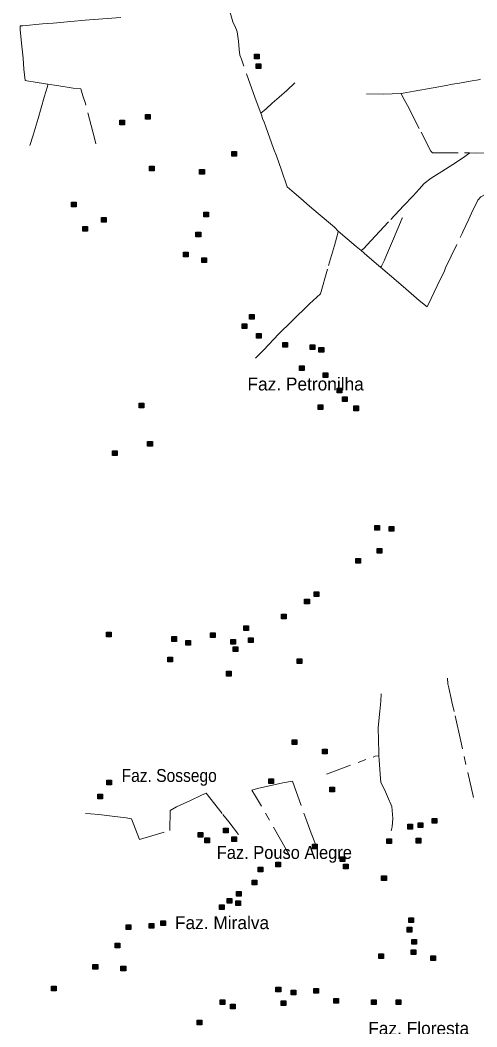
# Model space of a CAD drawing. Extents: x 393.5 to 446.9, y 8064.8 to 8120.4.
# Drawn here: x 401.4 to 407.05, y 8086.21 to 8098.67 of the extents above; entities that cross this region are included whole.
import ezdxf

# ---------------------------------------------------------------- set-up
doc = ezdxf.new("R2010")
doc.units = 0
doc.header["$LTSCALE"] = 0.064
doc.linetypes.add('DOT_DASHED', pattern=[7.7, 5, -1.2, 0.3, -1.2])
doc.layers.add('2', color=7, linetype='Continuous', lineweight=25)
doc.layers.add('22', color=7, linetype='DOT_DASHED', lineweight=13)
doc.layers.add('61', color=7, linetype='Continuous')

msp = doc.modelspace()

# ---------------------------------------------------------------- hatches: boundary and pattern name
at = {"layer": '2'}
for points in [[(404.302, 8098.2488), (404.36, 8098.2488), (404.36, 8098.1908), (404.302, 8098.1908)], [(404.3231, 8098.1292), (404.3811, 8098.1292), (404.3811, 8098.0712), (404.3231, 8098.0712)], [(402.9537, 8097.5023), (403.0117, 8097.5023), (403.0117, 8097.4443), (402.9537, 8097.4443)], [(402.6377, 8097.4316), (402.6957, 8097.4316), (402.6957, 8097.3736), (402.6377, 8097.3736)], [(404.0237, 8097.0426), (404.0817, 8097.0426), (404.0817, 8096.9846), (404.0237, 8096.9846)], [(403.0032, 8096.8617), (403.0612, 8096.8617), (403.0612, 8096.8037), (403.0032, 8096.8037)], [(403.6247, 8096.822), (403.6827, 8096.822), (403.6827, 8096.764), (403.6247, 8096.764)], [(402.0408, 8096.4174), (402.0988, 8096.4174), (402.0988, 8096.3594), (402.0408, 8096.3594)], [(402.4106, 8096.2273), (402.4686, 8096.2273), (402.4686, 8096.1693), (402.4106, 8096.1693)], [(403.6778, 8096.2912), (403.7358, 8096.2912), (403.7358, 8096.2332), (403.6778, 8096.2332)], [(402.1813, 8096.1145), (402.2393, 8096.1145), (402.2393, 8096.0565), (402.1813, 8096.0565)], [(403.5795, 8096.0448), (403.6375, 8096.0448), (403.6375, 8095.9868), (403.5795, 8095.9868)], [(403.4244, 8095.7975), (403.4824, 8095.7975), (403.4824, 8095.7395), (403.4244, 8095.7395)], [(403.65, 8095.7277), (403.708, 8095.7277), (403.708, 8095.6697), (403.65, 8095.6697)], [(404.2404, 8095.0263), (404.2984, 8095.0263), (404.2984, 8094.9683), (404.2404, 8094.9683)], [(404.1492, 8094.9105), (404.2072, 8094.9105), (404.2072, 8094.8525), (404.1492, 8094.8525)], [(404.3285, 8094.7903), (404.3865, 8094.7903), (404.3865, 8094.7323), (404.3285, 8094.7323)], [(404.6548, 8094.6775), (404.7128, 8094.6775), (404.7128, 8094.6195), (404.6548, 8094.6195)], [(404.9925, 8094.65), (405.0505, 8094.65), (405.0505, 8094.592), (404.9925, 8094.592)], [(405.1008, 8094.6177), (405.1588, 8094.6177), (405.1588, 8094.5597), (405.1008, 8094.5597)], [(404.859, 8094.3885), (404.917, 8094.3885), (404.917, 8094.3305), (404.859, 8094.3305)], [(405.1537, 8094.3047), (405.2117, 8094.3047), (405.2117, 8094.2467), (405.1537, 8094.2467)], [(405.324, 8094.1142), (405.382, 8094.1142), (405.382, 8094.0562), (405.324, 8094.0562)], [(405.3916, 8094.005), (405.4496, 8094.005), (405.4496, 8093.947), (405.3916, 8093.947)], [(402.8759, 8093.9275), (402.9339, 8093.9275), (402.9339, 8093.8695), (402.8759, 8093.8695)], [(405.0893, 8093.9068), (405.1473, 8093.9068), (405.1473, 8093.8488), (405.0893, 8093.8488)], [(405.5314, 8093.8928), (405.5894, 8093.8928), (405.5894, 8093.8348), (405.5314, 8093.8348)], [(402.5459, 8093.3388), (402.6039, 8093.3388), (402.6039, 8093.2808), (402.5459, 8093.2808)], [(402.9816, 8093.4521), (403.0396, 8093.4521), (403.0396, 8093.3941), (402.9816, 8093.3941)], [(405.792, 8092.414), (405.85, 8092.414), (405.85, 8092.356), (405.792, 8092.356)], [(405.9672, 8092.4), (406.0252, 8092.4), (406.0252, 8092.342), (405.9672, 8092.342)], [(405.8208, 8092.1275), (405.8788, 8092.1275), (405.8788, 8092.0695), (405.8208, 8092.0695)], [(405.5557, 8092.0035), (405.6137, 8092.0035), (405.6137, 8091.9455), (405.5557, 8091.9455)], [(405.0426, 8091.5927), (405.1006, 8091.5927), (405.1006, 8091.5347), (405.0426, 8091.5347)], [(404.9233, 8091.5012), (404.9813, 8091.5012), (404.9813, 8091.4432), (404.9233, 8091.4432)], [(404.6388, 8091.3169), (404.6968, 8091.3169), (404.6968, 8091.2589), (404.6388, 8091.2589)], [(402.4716, 8091.0928), (402.5296, 8091.0928), (402.5296, 8091.0348), (402.4716, 8091.0348)], [(404.1693, 8091.1691), (404.2273, 8091.1691), (404.2273, 8091.1111), (404.1693, 8091.1111)], [(403.2804, 8091.0368), (403.3384, 8091.0368), (403.3384, 8090.9788), (403.2804, 8090.9788)], [(403.4555, 8090.9884), (403.5135, 8090.9884), (403.5135, 8090.9304), (403.4555, 8090.9304)], [(403.7582, 8091.086), (403.8162, 8091.086), (403.8162, 8091.028), (403.7582, 8091.028)], [(404.0109, 8091.0018), (404.0689, 8091.0018), (404.0689, 8090.9438), (404.0109, 8090.9438)], [(404.2287, 8091.023), (404.2867, 8091.023), (404.2867, 8090.965), (404.2287, 8090.965)], [(404.0391, 8090.9105), (404.0971, 8090.9105), (404.0971, 8090.8525), (404.0391, 8090.8525)], [(403.2318, 8090.781), (403.2898, 8090.781), (403.2898, 8090.723), (403.2318, 8090.723)], [(404.8322, 8090.7629), (404.8902, 8090.7629), (404.8902, 8090.7049), (404.8322, 8090.7049)], [(403.9548, 8090.6076), (404.0128, 8090.6076), (404.0128, 8090.5496), (403.9548, 8090.5496)], [(404.7686, 8089.7584), (404.8266, 8089.7584), (404.8266, 8089.7004), (404.7686, 8089.7004)], [(405.1425, 8089.6457), (405.2005, 8089.6457), (405.2005, 8089.5877), (405.1425, 8089.5877)], [(402.4769, 8089.2584), (402.5349, 8089.2584), (402.5349, 8089.2004), (402.4769, 8089.2004)], [(404.4821, 8089.2773), (404.5401, 8089.2773), (404.5401, 8089.2193), (404.4821, 8089.2193)], [(405.2354, 8089.1725), (405.2934, 8089.1725), (405.2934, 8089.1145), (405.2354, 8089.1145)], [(402.3662, 8089.0853), (402.4242, 8089.0853), (402.4242, 8089.0273), (402.3662, 8089.0273)], [(406.3291, 8088.7332), (406.3871, 8088.7332), (406.3871, 8088.6752), (406.3291, 8088.6752)], [(406.4992, 8088.7842), (406.5572, 8088.7842), (406.5572, 8088.7262), (406.4992, 8088.7262)], [(403.608, 8088.6124), (403.666, 8088.6124), (403.666, 8088.5544), (403.608, 8088.5544)], [(403.9209, 8088.6675), (403.9789, 8088.6675), (403.9789, 8088.6095), (403.9209, 8088.6095)], [(406.1977, 8088.7131), (406.2557, 8088.7131), (406.2557, 8088.6551), (406.1977, 8088.6551)], [(403.6897, 8088.544), (403.7477, 8088.544), (403.7477, 8088.486), (403.6897, 8088.486)], [(404.0222, 8088.5586), (404.0802, 8088.5586), (404.0802, 8088.5006), (404.0222, 8088.5006)], [(405.9402, 8088.5332), (405.9982, 8088.5332), (405.9982, 8088.4752), (405.9402, 8088.4752)], [(406.3036, 8088.5398), (406.3616, 8088.5398), (406.3616, 8088.4818), (406.3036, 8088.4818)], [(405.0197, 8088.4675), (405.0777, 8088.4675), (405.0777, 8088.4095), (405.0197, 8088.4095)], [(404.5674, 8088.2454), (404.6254, 8088.2454), (404.6254, 8088.1874), (404.5674, 8088.1874)], [(405.3621, 8088.3107), (405.4201, 8088.3107), (405.4201, 8088.2527), (405.3621, 8088.2527)], [(404.3475, 8088.1816), (404.4055, 8088.1816), (404.4055, 8088.1236), (404.3475, 8088.1236)], [(405.4034, 8088.2187), (405.4614, 8088.2187), (405.4614, 8088.1607), (405.4034, 8088.1607)], [(404.2722, 8088.0235), (404.3302, 8088.0235), (404.3302, 8087.9655), (404.2722, 8087.9655)], [(405.8757, 8088.0757), (405.9337, 8088.0757), (405.9337, 8088.0177), (405.8757, 8088.0177)], [(404.0812, 8087.8829), (404.1392, 8087.8829), (404.1392, 8087.8249), (404.0812, 8087.8249)], [(403.9646, 8087.7946), (404.0226, 8087.7946), (404.0226, 8087.7366), (403.9646, 8087.7366)], [(404.0734, 8087.7653), (404.1314, 8087.7653), (404.1314, 8087.7073), (404.0734, 8087.7073)], [(403.8705, 8087.7147), (403.9285, 8087.7147), (403.9285, 8087.6567), (403.8705, 8087.6567)], [(403, 8087.4867), (403.058, 8087.4867), (403.058, 8087.4287), (403, 8087.4287)], [(403.1449, 8087.5175), (403.2029, 8087.5175), (403.2029, 8087.4595), (403.1449, 8087.4595)], [(406.2113, 8087.5568), (406.2693, 8087.5568), (406.2693, 8087.4988), (406.2113, 8087.4988)], [(402.7152, 8087.4706), (402.7732, 8087.4706), (402.7732, 8087.4126), (402.7152, 8087.4126)], [(406.1901, 8087.4378), (406.2481, 8087.4378), (406.2481, 8087.3798), (406.1901, 8087.3798)], [(402.5805, 8087.2434), (402.6385, 8087.2434), (402.6385, 8087.1854), (402.5805, 8087.1854)], [(406.247, 8087.2871), (406.305, 8087.2871), (406.305, 8087.2291), (406.247, 8087.2291)], [(405.8389, 8087.1089), (405.8969, 8087.1089), (405.8969, 8087.0509), (405.8389, 8087.0509)], [(406.2407, 8087.1575), (406.2987, 8087.1575), (406.2987, 8087.0995), (406.2407, 8087.0995)], [(406.4839, 8087.084), (406.5419, 8087.084), (406.5419, 8087.026), (406.4839, 8087.026)], [(402.3055, 8086.9766), (402.3635, 8086.9766), (402.3635, 8086.9186), (402.3055, 8086.9186)], [(402.6517, 8086.9574), (402.7097, 8086.9574), (402.7097, 8086.8994), (402.6517, 8086.8994)], [(401.7937, 8086.708), (401.8517, 8086.708), (401.8517, 8086.65), (401.7937, 8086.65)], [(404.5689, 8086.6965), (404.6269, 8086.6965), (404.6269, 8086.6385), (404.5689, 8086.6385)], [(404.7581, 8086.6615), (404.8161, 8086.6615), (404.8161, 8086.6035), (404.7581, 8086.6035)], [(405.0387, 8086.6824), (405.0967, 8086.6824), (405.0967, 8086.6244), (405.0387, 8086.6244)], [(403.8774, 8086.5412), (403.9354, 8086.5412), (403.9354, 8086.4832), (403.8774, 8086.4832)], [(404.0075, 8086.4862), (404.0655, 8086.4862), (404.0655, 8086.4282), (404.0075, 8086.4282)], [(404.6317, 8086.5284), (404.6897, 8086.5284), (404.6897, 8086.4704), (404.6317, 8086.4704)], [(405.2839, 8086.5561), (405.3419, 8086.5561), (405.3419, 8086.4981), (405.2839, 8086.4981)], [(405.7515, 8086.5395), (405.8095, 8086.5395), (405.8095, 8086.4815), (405.7515, 8086.4815)], [(406.0551, 8086.5412), (406.1131, 8086.5412), (406.1131, 8086.4832), (406.0551, 8086.4832)], [(403.5933, 8086.2898), (403.6513, 8086.2898), (403.6513, 8086.2318), (403.5933, 8086.2318)]]:
    msp.add_hatch(color=256, dxfattribs=at).paths.add_polyline_path(points)

# ---------------------------------------------------------------- linework, layer by layer
for points in [[(404.302, 8098.2488), (404.36, 8098.2488), (404.36, 8098.1908), (404.302, 8098.1908)], [(404.3231, 8098.1292), (404.3811, 8098.1292), (404.3811, 8098.0712), (404.3231, 8098.0712)], [(402.9537, 8097.5023), (403.0117, 8097.5023), (403.0117, 8097.4443), (402.9537, 8097.4443)], [(402.6377, 8097.4316), (402.6957, 8097.4316), (402.6957, 8097.3736), (402.6377, 8097.3736)], [(404.0237, 8097.0426), (404.0817, 8097.0426), (404.0817, 8096.9846), (404.0237, 8096.9846)], [(403.0032, 8096.8617), (403.0612, 8096.8617), (403.0612, 8096.8037), (403.0032, 8096.8037)], [(403.6247, 8096.822), (403.6827, 8096.822), (403.6827, 8096.764), (403.6247, 8096.764)], [(402.0408, 8096.4174), (402.0988, 8096.4174), (402.0988, 8096.3594), (402.0408, 8096.3594)], [(402.4106, 8096.2273), (402.4686, 8096.2273), (402.4686, 8096.1693), (402.4106, 8096.1693)], [(403.6778, 8096.2912), (403.7358, 8096.2912), (403.7358, 8096.2332), (403.6778, 8096.2332)], [(402.1813, 8096.1145), (402.2393, 8096.1145), (402.2393, 8096.0565), (402.1813, 8096.0565)], [(403.5795, 8096.0448), (403.6375, 8096.0448), (403.6375, 8095.9868), (403.5795, 8095.9868)], [(403.4244, 8095.7975), (403.4824, 8095.7975), (403.4824, 8095.7395), (403.4244, 8095.7395)], [(403.65, 8095.7277), (403.708, 8095.7277), (403.708, 8095.6697), (403.65, 8095.6697)], [(404.2404, 8095.0263), (404.2984, 8095.0263), (404.2984, 8094.9683), (404.2404, 8094.9683)], [(404.1492, 8094.9105), (404.2072, 8094.9105), (404.2072, 8094.8525), (404.1492, 8094.8525)], [(404.3285, 8094.7903), (404.3865, 8094.7903), (404.3865, 8094.7323), (404.3285, 8094.7323)], [(404.6548, 8094.6775), (404.7128, 8094.6775), (404.7128, 8094.6195), (404.6548, 8094.6195)], [(404.9925, 8094.65), (405.0505, 8094.65), (405.0505, 8094.592), (404.9925, 8094.592)], [(405.1008, 8094.6177), (405.1588, 8094.6177), (405.1588, 8094.5597), (405.1008, 8094.5597)], [(404.859, 8094.3885), (404.917, 8094.3885), (404.917, 8094.3305), (404.859, 8094.3305)], [(405.1537, 8094.3047), (405.2117, 8094.3047), (405.2117, 8094.2467), (405.1537, 8094.2467)], [(405.324, 8094.1142), (405.382, 8094.1142), (405.382, 8094.0562), (405.324, 8094.0562)], [(405.3916, 8094.005), (405.4496, 8094.005), (405.4496, 8093.947), (405.3916, 8093.947)], [(402.8759, 8093.9275), (402.9339, 8093.9275), (402.9339, 8093.8695), (402.8759, 8093.8695)], [(405.0893, 8093.9068), (405.1473, 8093.9068), (405.1473, 8093.8488), (405.0893, 8093.8488)], [(405.5314, 8093.8928), (405.5894, 8093.8928), (405.5894, 8093.8348), (405.5314, 8093.8348)], [(402.5459, 8093.3388), (402.6039, 8093.3388), (402.6039, 8093.2808), (402.5459, 8093.2808)], [(402.9816, 8093.4521), (403.0396, 8093.4521), (403.0396, 8093.3941), (402.9816, 8093.3941)], [(405.792, 8092.414), (405.85, 8092.414), (405.85, 8092.356), (405.792, 8092.356)], [(405.9672, 8092.4), (406.0252, 8092.4), (406.0252, 8092.342), (405.9672, 8092.342)], [(405.8208, 8092.1275), (405.8788, 8092.1275), (405.8788, 8092.0695), (405.8208, 8092.0695)], [(405.5557, 8092.0035), (405.6137, 8092.0035), (405.6137, 8091.9455), (405.5557, 8091.9455)], [(405.0426, 8091.5927), (405.1006, 8091.5927), (405.1006, 8091.5347), (405.0426, 8091.5347)], [(404.9233, 8091.5012), (404.9813, 8091.5012), (404.9813, 8091.4432), (404.9233, 8091.4432)], [(404.6388, 8091.3169), (404.6968, 8091.3169), (404.6968, 8091.2589), (404.6388, 8091.2589)], [(402.4716, 8091.0928), (402.5296, 8091.0928), (402.5296, 8091.0348), (402.4716, 8091.0348)], [(404.1693, 8091.1691), (404.2273, 8091.1691), (404.2273, 8091.1111), (404.1693, 8091.1111)], [(403.2804, 8091.0368), (403.3384, 8091.0368), (403.3384, 8090.9788), (403.2804, 8090.9788)], [(403.4555, 8090.9884), (403.5135, 8090.9884), (403.5135, 8090.9304), (403.4555, 8090.9304)], [(403.7582, 8091.086), (403.8162, 8091.086), (403.8162, 8091.028), (403.7582, 8091.028)], [(404.0109, 8091.0018), (404.0689, 8091.0018), (404.0689, 8090.9438), (404.0109, 8090.9438)], [(404.2287, 8091.023), (404.2867, 8091.023), (404.2867, 8090.965), (404.2287, 8090.965)], [(404.0391, 8090.9105), (404.0971, 8090.9105), (404.0971, 8090.8525), (404.0391, 8090.8525)], [(403.2318, 8090.781), (403.2898, 8090.781), (403.2898, 8090.723), (403.2318, 8090.723)], [(404.8322, 8090.7629), (404.8902, 8090.7629), (404.8902, 8090.7049), (404.8322, 8090.7049)], [(403.9548, 8090.6076), (404.0128, 8090.6076), (404.0128, 8090.5496), (403.9548, 8090.5496)], [(404.7686, 8089.7584), (404.8266, 8089.7584), (404.8266, 8089.7004), (404.7686, 8089.7004)], [(405.1425, 8089.6457), (405.2005, 8089.6457), (405.2005, 8089.5877), (405.1425, 8089.5877)], [(402.4769, 8089.2584), (402.5349, 8089.2584), (402.5349, 8089.2004), (402.4769, 8089.2004)], [(404.4821, 8089.2773), (404.5401, 8089.2773), (404.5401, 8089.2193), (404.4821, 8089.2193)], [(405.2354, 8089.1725), (405.2934, 8089.1725), (405.2934, 8089.1145), (405.2354, 8089.1145)], [(402.3662, 8089.0853), (402.4242, 8089.0853), (402.4242, 8089.0273), (402.3662, 8089.0273)], [(406.3291, 8088.7332), (406.3871, 8088.7332), (406.3871, 8088.6752), (406.3291, 8088.6752)], [(406.4992, 8088.7842), (406.5572, 8088.7842), (406.5572, 8088.7262), (406.4992, 8088.7262)], [(403.608, 8088.6124), (403.666, 8088.6124), (403.666, 8088.5544), (403.608, 8088.5544)], [(403.9209, 8088.6675), (403.9789, 8088.6675), (403.9789, 8088.6095), (403.9209, 8088.6095)], [(406.1977, 8088.7131), (406.2557, 8088.7131), (406.2557, 8088.6551), (406.1977, 8088.6551)], [(403.6897, 8088.544), (403.7477, 8088.544), (403.7477, 8088.486), (403.6897, 8088.486)], [(404.0222, 8088.5586), (404.0802, 8088.5586), (404.0802, 8088.5006), (404.0222, 8088.5006)], [(405.9402, 8088.5332), (405.9982, 8088.5332), (405.9982, 8088.4752), (405.9402, 8088.4752)], [(406.3036, 8088.5398), (406.3616, 8088.5398), (406.3616, 8088.4818), (406.3036, 8088.4818)], [(405.0197, 8088.4675), (405.0777, 8088.4675), (405.0777, 8088.4095), (405.0197, 8088.4095)], [(404.5674, 8088.2454), (404.6254, 8088.2454), (404.6254, 8088.1874), (404.5674, 8088.1874)], [(405.3621, 8088.3107), (405.4201, 8088.3107), (405.4201, 8088.2527), (405.3621, 8088.2527)], [(404.3475, 8088.1816), (404.4055, 8088.1816), (404.4055, 8088.1236), (404.3475, 8088.1236)], [(405.4034, 8088.2187), (405.4614, 8088.2187), (405.4614, 8088.1607), (405.4034, 8088.1607)], [(404.2722, 8088.0235), (404.3302, 8088.0235), (404.3302, 8087.9655), (404.2722, 8087.9655)], [(405.8757, 8088.0757), (405.9337, 8088.0757), (405.9337, 8088.0177), (405.8757, 8088.0177)], [(404.0812, 8087.8829), (404.1392, 8087.8829), (404.1392, 8087.8249), (404.0812, 8087.8249)], [(403.9646, 8087.7946), (404.0226, 8087.7946), (404.0226, 8087.7366), (403.9646, 8087.7366)], [(404.0734, 8087.7653), (404.1314, 8087.7653), (404.1314, 8087.7073), (404.0734, 8087.7073)], [(403.8705, 8087.7147), (403.9285, 8087.7147), (403.9285, 8087.6567), (403.8705, 8087.6567)], [(403, 8087.4867), (403.058, 8087.4867), (403.058, 8087.4287), (403, 8087.4287)], [(403.1449, 8087.5175), (403.2029, 8087.5175), (403.2029, 8087.4595), (403.1449, 8087.4595)], [(406.2113, 8087.5568), (406.2693, 8087.5568), (406.2693, 8087.4988), (406.2113, 8087.4988)], [(402.7152, 8087.4706), (402.7732, 8087.4706), (402.7732, 8087.4126), (402.7152, 8087.4126)], [(406.1901, 8087.4378), (406.2481, 8087.4378), (406.2481, 8087.3798), (406.1901, 8087.3798)], [(402.5805, 8087.2434), (402.6385, 8087.2434), (402.6385, 8087.1854), (402.5805, 8087.1854)], [(406.247, 8087.2871), (406.305, 8087.2871), (406.305, 8087.2291), (406.247, 8087.2291)], [(405.8389, 8087.1089), (405.8969, 8087.1089), (405.8969, 8087.0509), (405.8389, 8087.0509)], [(406.2407, 8087.1575), (406.2987, 8087.1575), (406.2987, 8087.0995), (406.2407, 8087.0995)], [(406.4839, 8087.084), (406.5419, 8087.084), (406.5419, 8087.026), (406.4839, 8087.026)], [(402.3055, 8086.9766), (402.3635, 8086.9766), (402.3635, 8086.9186), (402.3055, 8086.9186)], [(402.6517, 8086.9574), (402.7097, 8086.9574), (402.7097, 8086.8994), (402.6517, 8086.8994)], [(401.7937, 8086.708), (401.8517, 8086.708), (401.8517, 8086.65), (401.7937, 8086.65)], [(404.5689, 8086.6965), (404.6269, 8086.6965), (404.6269, 8086.6385), (404.5689, 8086.6385)], [(404.7581, 8086.6615), (404.8161, 8086.6615), (404.8161, 8086.6035), (404.7581, 8086.6035)], [(405.0387, 8086.6824), (405.0967, 8086.6824), (405.0967, 8086.6244), (405.0387, 8086.6244)], [(403.8774, 8086.5412), (403.9354, 8086.5412), (403.9354, 8086.4832), (403.8774, 8086.4832)], [(404.0075, 8086.4862), (404.0655, 8086.4862), (404.0655, 8086.4282), (404.0075, 8086.4282)], [(404.6317, 8086.5284), (404.6897, 8086.5284), (404.6897, 8086.4704), (404.6317, 8086.4704)], [(405.2839, 8086.5561), (405.3419, 8086.5561), (405.3419, 8086.4981), (405.2839, 8086.4981)], [(405.7515, 8086.5395), (405.8095, 8086.5395), (405.8095, 8086.4815), (405.7515, 8086.4815)], [(406.0551, 8086.5412), (406.1131, 8086.5412), (406.1131, 8086.4832), (406.0551, 8086.4832)], [(403.5933, 8086.2898), (403.6513, 8086.2898), (403.6513, 8086.2318), (403.5933, 8086.2318)]]:
    msp.add_lwpolyline(points, close=True, dxfattribs=at)
at = {"layer": '22'}
for p, q in [((401.7479, 8097.8754), (401.7454, 8097.8759)), ((406.1156, 8097.7635), (406.1122, 8097.7633)), ((404.3797, 8097.5196), (404.3797, 8097.5197)), ((405.6226, 8095.8167), (405.6227, 8095.8166))]:
    msp.add_line(p, q, dxfattribs=at)
for points in [[(404.0701, 8098.5784), (404.0368, 8098.651), (404.0105, 8098.737), (403.9995, 8098.775), (403.9951, 8098.8698), (404.0039, 8098.9048), (404.0331, 8098.9515), (404.0433, 8098.9617), (404.0608, 8098.985), (404.0615, 8098.9848)], [(402.6519, 8098.7019), (402.4829, 8098.6906), (402.2079, 8098.6703), (402.032, 8098.6546), (401.8134, 8098.6343), (401.6804, 8098.6253), (401.4392, 8098.6005), (401.4047, 8098.5984)], [(401.7454, 8097.8759), (401.7165, 8097.8816), (401.5924, 8097.9007), (401.4891, 8097.9197), (401.4668, 8097.9245), (401.4509, 8098.0612), (401.4429, 8098.201), (401.4199, 8098.3838), (401.4064, 8098.5538), (401.4047, 8098.5984)], [(404.3797, 8097.5197), (404.313, 8097.7054), (404.1411, 8098.1866), (404.1221, 8098.238), (404.1119, 8098.308), (404.1046, 8098.4086), (404.09, 8098.5238), (404.0813, 8098.5515), (404.0701, 8098.5784)], [(401.5247, 8097.118), (401.5651, 8097.2442), (401.6271, 8097.4524), (401.7028, 8097.7162), (401.7433, 8097.8465), (401.7476, 8097.8736), (401.7479, 8097.8754)], [(402.1793, 8097.7334), (402.1569, 8097.8195), (402.0615, 8097.829), (401.8563, 8097.8624), (401.7479, 8097.8754)], [(404.3797, 8097.5196), (404.4474, 8097.5706), (404.5233, 8097.6435), (404.608, 8097.7178), (404.7028, 8097.7995), (404.8021, 8097.8943)], [(406.1156, 8097.7635), (406.1421, 8097.7641), (406.2791, 8097.7908), (406.5127, 8097.832), (406.6751, 8097.8605), (406.7514, 8097.8762), (406.839, 8097.8918), (406.9701, 8097.916), (407.0726, 8097.9331), (407.0988, 8097.9388)], [(402.3399, 8097.1377), (402.3224, 8097.2108), (402.2124, 8097.6367), (402.1793, 8097.7334)], [(406.1122, 8097.7633), (405.8988, 8097.7539), (405.688, 8097.7596)], [(406.1156, 8097.7635), (406.1323, 8097.7234), (406.1955, 8097.6117), (406.3631, 8097.285), (406.4848, 8097.0481), (406.5033, 8097.0253), (406.9016, 8097.0264), (406.9634, 8097.0253)], [(405.3393, 8096.0593), (405.2916, 8096.1054), (405.0902, 8096.276), (404.9837, 8096.3649), (404.8742, 8096.4611), (404.793, 8096.53), (404.7084, 8096.6058), (404.6354, 8096.8143), (404.5741, 8096.9893), (404.5381, 8097.0803), (404.4444, 8097.3485), (404.4225, 8097.4083), (404.4034, 8097.4535), (404.3891, 8097.4994), (404.3797, 8097.5196)], [(405.6226, 8095.8167), (405.6563, 8095.8418), (405.7438, 8095.9374), (405.9904, 8096.2012), (406.148, 8096.371), (406.2635, 8096.4947), (406.3394, 8096.5787), (406.4013, 8096.6463), (406.4871, 8096.7139), (406.6191, 8096.7963), (406.7544, 8096.8837), (406.8864, 8096.9711), (406.9376, 8097.0074), (406.9619, 8097.0243), (406.9627, 8097.0248), (406.9634, 8097.0253)], [(406.9634, 8097.0253), (407.0455, 8097.025), (407.2036, 8097.0264)], [(406.8717, 8096.0305), (406.8807, 8096.0507), (406.956, 8096.2069), (406.9879, 8096.2797), (407.0671, 8096.443), (407.1026, 8096.4806), (407.2329, 8096.5534), (407.4794, 8096.6886), (407.5786, 8096.7482)], [(405.8624, 8095.6123), (405.8755, 8095.6242), (405.9062, 8095.6919), (405.9355, 8095.7595), (406.0217, 8095.9607), (406.1294, 8096.2168), (406.1333, 8096.2219)], [(404.3149, 8094.4838), (404.4134, 8094.5823), (404.6031, 8094.7866), (404.7607, 8094.9392), (404.9854, 8095.1558), (405.1174, 8095.2795), (405.218, 8095.6323), (405.2923, 8095.8813), (405.3327, 8096.033), (405.3393, 8096.0592), (405.3393, 8096.0593)], [(405.3393, 8096.0593), (405.5626, 8095.8677), (405.6226, 8095.8167)], [(405.8615, 8095.6115), (406.0538, 8095.4477), (406.1764, 8095.3431), (406.3386, 8095.2001), (406.4388, 8095.121), (406.4861, 8095.2244), (406.5615, 8095.3788), (406.6522, 8095.5651), (406.6657, 8095.6026), (406.859, 8096.0035), (406.8717, 8096.0305)], [(405.6227, 8095.8166), (405.6929, 8095.7567), (405.7836, 8095.6763), (405.8359, 8095.6332), (405.8607, 8095.6121), (405.8615, 8095.6115), (405.8624, 8095.6123)], [(406.7444, 8090.2292), (406.7354, 8090.2717), (406.7059, 8090.4023), (406.6934, 8090.4512), (406.689, 8090.5245)], [(405.8427, 8089.5661), (405.8427, 8089.5979), (405.8326, 8089.9126), (405.8525, 8090.1134), (405.8664, 8090.2387), (405.8704, 8090.3282)], [(407.0107, 8089.0435), (406.8533, 8089.7443), (406.7734, 8090.1094), (406.7444, 8090.2292)], [(405.1919, 8089.3354), (405.7691, 8089.5462), (405.7969, 8089.5561), (405.8427, 8089.5621), (405.8427, 8089.5661)], [(405.9482, 8089.057), (405.9103, 8089.1426), (405.8666, 8089.232), (405.8586, 8089.3354), (405.8447, 8089.5124), (405.8427, 8089.5621)], [(404.7245, 8088.3525), (404.6957, 8088.3997), (404.317, 8089.0622), (404.2698, 8089.1381), (404.3417, 8089.1565), (404.6516, 8089.2263), (404.7727, 8089.2488), (404.9379, 8088.7832), (405.0036, 8088.6027), (405.057, 8088.4694)], [(402.2141, 8088.849), (402.2736, 8088.8449), (402.3763, 8088.8347), (402.5425, 8088.8121), (402.7149, 8088.7937), (402.7827, 8088.7814), (402.8792, 8088.527), (403.2548, 8088.6378), (403.2617, 8088.8853), (403.3397, 8088.9284), (403.5101, 8089.0063), (403.6456, 8089.0761), (403.7071, 8089.0986), (403.9124, 8088.8361), (403.9853, 8088.7438), (404.1043, 8088.588)], [(405.994, 8088.6334), (406.0059, 8088.6811), (406.0139, 8088.7845), (406, 8088.9337), (405.9482, 8089.057)]]:
    msp.add_lwpolyline(points, dxfattribs=at)

# ---------------------------------------------------------------- texts
at = {"layer": '61'}
for s, p in [('Faz. Petronilha', (404.2159, 8094.0849)), ('Faz. Miralva', (403.3189, 8087.4157)), ('Faz. Floresta', (405.7098, 8086.1071))]:
    msp.add_text(s, height=0.16, dxfattribs=at).set_placement(p)
for s, width, p in [('Faz. Sossego', 0.9, (402.6594, 8089.2379)), ('Faz. Pouso Alegre', 0.95, (403.8361, 8088.2848))]:
    msp.add_text(s, height=0.16, dxfattribs=dict(at, width=width)).set_placement(p)

doc.saveas('drawing.dxf')
